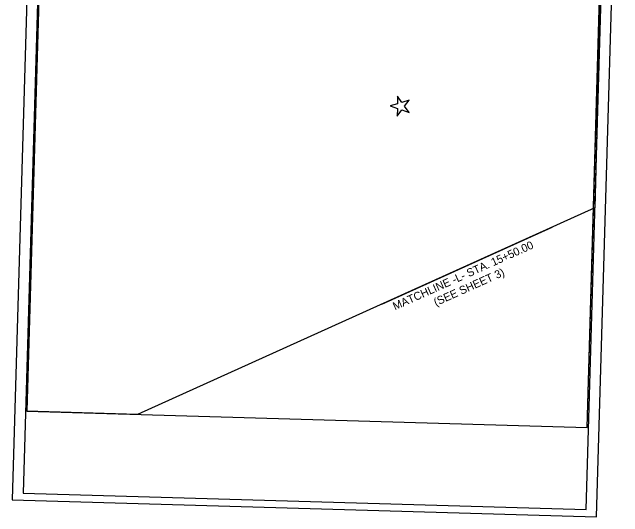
# Model space of a CAD drawing. Extents: x 2096999 to 2102576, y 682920 to 687015.
# Drawn here: x 2096999 to 2098143, y 685126 to 686071 of the extents above; entities that cross this region are included whole.
import ezdxf

# ---------------------------------------------------------------- set-up
doc = ezdxf.new("R2010")
doc.units = 0
for name, color, linetype in [('Default', 7, 'Continuous'), ('Matchline', 7, 'Continuous'), ('Matchline Text', 7, 'Continuous'), ('Scratch_Level_0', 7, 'Continuous'), ('Scratch_Level_2', 7, 'Continuous'), ('Sheet Plan CELL', 7, 'Continuous'), ('Sheet Plot Border Inside CELL', 7, 'Continuous'), ('Sheet Plot Border Outside CELL', 7, 'Continuous')]:
    doc.layers.add(name, color=color, linetype=linetype)

msp = doc.modelspace()

# ---------------------------------------------------------------- linework, layer by layer
at = {"layer": 'Default'}
msp.add_lwpolyline([(2097729.5, 685901.9), (2097721.4, 685913.6), (2097721.1, 685899.4), (2097707.5, 685895.2), (2097720.9, 685890.6), (2097720.7, 685876.3), (2097729.2, 685887.7), (2097742.7, 685883), (2097734.5, 685894.7), (2097743.1, 685906.1), (2097729.5, 685901.9)], dxfattribs=at)
at = {"layer": 'Matchline'}
msp.add_line((2097692.1, 685524.4), (2098011.1, 685668.4), dxfattribs=at)
at = {"layer": 'Scratch_Level_0'}
msp.add_line((2098076.3, 685293.3), (2098110.1, 686454.3), dxfattribs=at)
at = {"layer": 'Scratch_Level_2'}
msp.add_lwpolyline([(2097234.3, 685317.8), (2097026.8, 685323.8), (2097058.7, 686423.2), (2097059.3, 686437), (2097065.1, 686636.7), (2097214.2, 686632.3), (2097231.8, 686631.8), (2097295.9, 686629.9), (2097298.8, 686729.8), (2098044.6, 686708.1), (2098037.2, 686456.5), (2098110.1, 686454.3), (2098090.8, 685704.4)], close=True, dxfattribs=at)
at = {"layer": 'Sheet Plan CELL'}
msp.add_lwpolyline([(2097070.6, 686823.4), (2097026.8, 685324), (2098076.3, 685293.3), (2098120.2, 686792.7)], close=True, dxfattribs=at)
msp.add_lwpolyline([(2097070.6, 686823.4), (2097026.8, 685324), (2098076.3, 685293.3), (2098120.2, 686792.7)], close=True, dxfattribs=at)
at = {"layer": 'Sheet Plot Border Inside CELL'}
msp.add_lwpolyline([(2098074.3, 685139.8), (2098123, 686805.1), (2097068.5, 686835.9), (2097019.8, 685170.6)], close=True, dxfattribs=at)
msp.add_lwpolyline([(2098074.3, 685139.8), (2098123, 686805.1), (2097068.5, 686835.9), (2097019.8, 685170.6)], close=True, dxfattribs=at)
at = {"layer": 'Sheet Plot Border Outside CELL'}
msp.add_lwpolyline([(2098094, 685126.2), (2098143.2, 686809), (2097048.6, 686841), (2096999.4, 685158.2)], close=True, dxfattribs=at)
msp.add_lwpolyline([(2098094, 685126.2), (2098143.2, 686809), (2097048.6, 686841), (2096999.4, 685158.2)], close=True, dxfattribs=at)

# ---------------------------------------------------------------- texts
at = {"layer": 'Matchline Text'}
for s, p in [('MATCHLINE -L- STA. 15+50.00', (2097716.4, 685512.6)), ('(SEE SHEET 3)', (2097793, 685520.2))]:
    msp.add_text(s, height=15, rotation=24.122, dxfattribs=at).set_placement(p)

doc.saveas('drawing.dxf')
